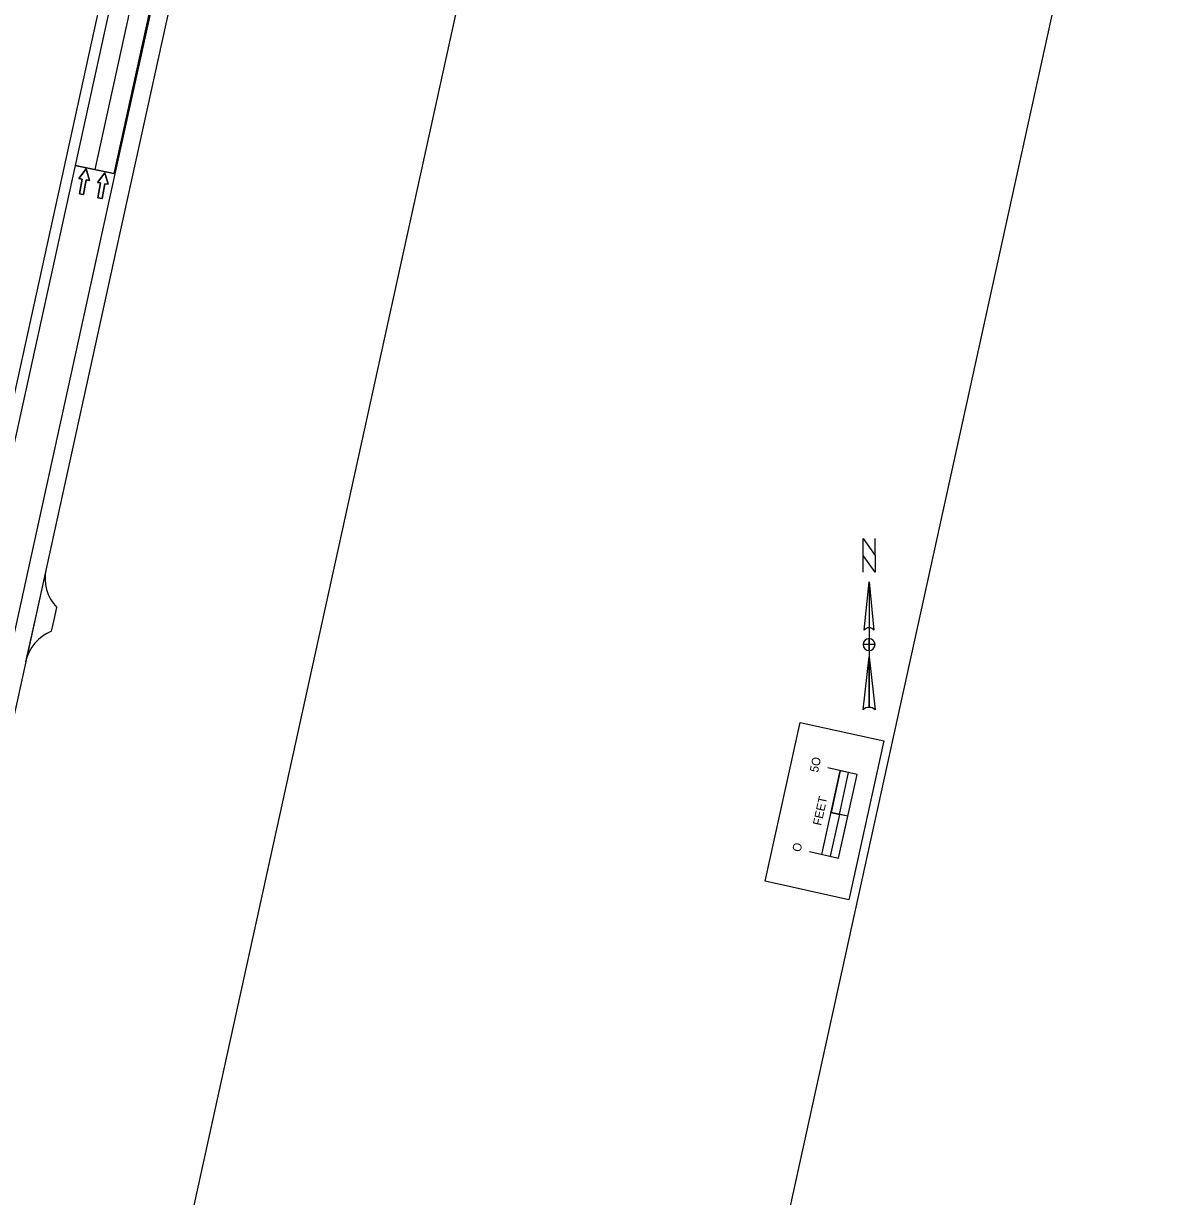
# Model space of a CAD drawing. Extents: x 14104283 to 14129344, y 8637090 to 8673339.
# Drawn here: x 14108148 to 14108813, y 8640210 to 8640895 of the extents above; entities that cross this region are included whole.
import ezdxf

# ---------------------------------------------------------------- set-up
doc = ezdxf.new("R2010")
doc.units = 0
for name, color, linetype in [('Cell', 7, 'Continuous'), ('Default', 7, 'Continuous'), ('dsnCellsNorthArrow', 7, 'Continuous'), ('dsnCellsScaleBlock', 7, 'Continuous'), ('dsnNonPlotable', 7, 'Continuous'), ('dsnPaintPlaceBrokenLineWhite', 7, 'Continuous'), ('dsnPaintPlaceEdgeLineRightWhite', 7, 'Continuous'), ('dsnShadingGranular', 7, 'Continuous'), ('dsnShadingPaved', 7, 'Continuous'), ('dsnStgShadingPrevPav', 7, 'Continuous')]:
    doc.layers.add(name, color=color, linetype=linetype)

msp = doc.modelspace()

# ---------------------------------------------------------------- linework, layer by layer
at = {"layer": 'Cell'}
for points in [[(14108183.04, 8640795.5), (14108180.58, 8640795.95), (14108182.15, 8640804.56), (14108180.3, 8640804.9), (14108184.49, 8640810.49), (14108186.45, 8640803.78), (14108184.6, 8640804.11)], [(14108193.92, 8640793.22), (14108191.46, 8640793.67), (14108193.03, 8640802.28), (14108191.19, 8640802.62), (14108195.38, 8640808.21), (14108197.33, 8640801.5), (14108195.49, 8640801.83)]]:
    msp.add_lwpolyline(points, close=True, dxfattribs=at)
for points in [[(14108184.6, 8640804.11), (14108186.45, 8640803.78), (14108184.49, 8640810.49), (14108180.3, 8640804.9), (14108182.15, 8640804.56), (14108180.58, 8640795.95), (14108183.04, 8640795.5), (14108184.6, 8640804.11)], [(14108195.49, 8640801.83), (14108197.33, 8640801.5), (14108195.38, 8640808.21), (14108191.19, 8640802.62), (14108193.03, 8640802.28), (14108191.46, 8640793.67), (14108193.92, 8640793.22), (14108195.49, 8640801.83)]]:
    msp.add_lwpolyline(points, dxfattribs=at)
at = {"layer": 'Default'}
for p, q in [((14108178.07, 8640812.51), (14108054.09, 8640248.16)), ((14108201.57, 8640807.64), (14108178.07, 8640812.51)), ((14108077.53, 8640243.01), (14108201.57, 8640807.64))]:
    msp.add_line(p, q, dxfattribs=at)
at = {"layer": 'dsnCellsNorthArrow'}
for p, q in [((14108641.86, 8640569.29), (14108644.67, 8640541.12)), ((14108641.86, 8640569.29), (14108641.86, 8640496.05)), ((14108639.04, 8640541.12), (14108639.04, 8640541.12)), ((14108639.15, 8640541.38), (14108639.67, 8640541.97)), ((14108638.34, 8640494.64), (14108641.86, 8640525.63)), ((14108641.86, 8640529.15), (14108641.86, 8640529.15))]:
    msp.add_line(p, q, dxfattribs=at)
msp.add_lwpolyline([(14108645.38, 8640574.93), (14108638.34, 8640584.79), (14108638.34, 8640594.65), (14108645.38, 8640584.79)], close=True, dxfattribs=at)
for points in [[(14108638.34, 8640574.93), (14108638.34, 8640594.65), (14108645.38, 8640584.79), (14108645.38, 8640594.65)], [(14108639.04, 8640541.12), (14108641.86, 8640569.29), (14108641.86, 8640542.53)], [(14108641.86, 8640529.15), (14108641.86, 8640532.67), (14108638.34, 8640532.67)], [(14108645.38, 8640532.67), (14108641.86, 8640532.67), (14108641.86, 8640536.19)], [(14108641.86, 8640496.05), (14108641.86, 8640525.63), (14108645.38, 8640494.64)]]:
    msp.add_lwpolyline(points, dxfattribs=at)
for centre, radius, start, end in [((14108641.86, 8640539.01), 3.52, 90.02039, 143.12574), ((14108641.86, 8640539.01), 3.52, 36.84806, 90.02184), ((14108641.86, 8640532.67), 3.52, 90, 180), ((14108641.86, 8640532.67), 3.52, 180, 270), ((14108641.86, 8640532.67), 3.52, 0, 90), ((14108641.86, 8640532.67), 3.52, 270, 360), ((14108641.86, 8640490.95), 5.1, 89.98939, 133.61895), ((14108641.86, 8640490.94), 5.11, 46.40206, 90.00064)]:
    msp.add_arc(centre, radius, start, end, dxfattribs=at)
at = {"layer": 'dsnCellsScaleBlock'}
msp.add_line((14108629.49, 8640432.47), (14108619.72, 8640434.62), dxfattribs=at)
msp.add_line((14108629.49, 8640432.47), (14108619.72, 8640434.62), dxfattribs=at)
for points in [[(14108630.04, 8640383.72), (14108581.2, 8640394.45), (14108601.59, 8640487.23), (14108650.42, 8640476.5)], [(14108581.2, 8640394.45), (14108601.59, 8640487.23), (14108650.42, 8640476.5), (14108630.04, 8640383.72)], [(14108630.04, 8640383.72), (14108581.2, 8640394.45), (14108601.59, 8640487.23), (14108650.42, 8640476.5)], [(14108624.57, 8640433.55), (14108629.93, 8640457.97), (14108625.08, 8640459.04), (14108619.72, 8640434.62)], [(14108624.12, 8640408.05), (14108629.49, 8640432.47), (14108624.57, 8640433.55), (14108619.2, 8640409.13)]]:
    msp.add_lwpolyline(points, close=True, dxfattribs=at)
for points in [[(14108607.03, 8640411.81), (14108624.12, 8640408.05), (14108634.85, 8640456.89), (14108617.76, 8640460.64)], [(14108614.35, 8640410.2), (14108625.08, 8640459.04)]]:
    msp.add_lwpolyline(points, dxfattribs=at)
at = {"layer": 'dsnNonPlotable'}
for points in [[(14107490.45, 8639880.3), (14107826.84, 8641411.28), (14108813.31, 8641194.53), (14108476.92, 8639663.55)], [(14107651.31, 8639844.94), (14107987.7, 8641375.92), (14108480.93, 8641267.54), (14108144.54, 8639736.56)]]:
    msp.add_lwpolyline(points, close=True, dxfattribs=at)
at = {"layer": 'dsnPaintPlaceBrokenLineWhite'}
msp.add_line((14108189.82, 8640810.08), (14108306.37, 8641340.66), dxfattribs=at)
at = {"layer": 'dsnPaintPlaceEdgeLineRightWhite'}
msp.add_line((14108201.57, 8640807.63), (14108723.98, 8643185.75), dxfattribs=at)
at = {"layer": 'dsnShadingGranular'}
for p, q in [((14108161.12, 8640576.89), (14108155.11, 8640549.54)), ((14108155.11, 8640549.54), (14108149.21, 8640522.69))]:
    msp.add_line(p, q, dxfattribs=at)
at = {"layer": 'dsnShadingPaved'}
for p, q in [((14108200.83, 8640807.79), (14108723.98, 8643185.75)), ((14108199.55, 8640910.32), (14108178.07, 8640812.51)), ((14108178.07, 8640812.51), (14108200.83, 8640807.79))]:
    msp.add_line(p, q, dxfattribs=at)
at = {"layer": 'dsnStgShadingPrevPav'}
for p, q in [((14108161.12, 8640576.89), (14108155.11, 8640549.54)), ((14108165.86, 8640547.18), (14108167.42, 8640554.3)), ((14108155.11, 8640549.54), (14108149.21, 8640522.69)), ((14108164.4, 8640540.56), (14108165.86, 8640547.18))]:
    msp.add_line(p, q, dxfattribs=at)
msp.add_lwpolyline([(14108081.5, 8640400.87), (14108123.34, 8640591.33), (14108126.55, 8640605.98), (14108216.67, 8641016.2), (14108268.16, 8641250.61), (14108382.95, 8641773.15), (14108422.02, 8641764.57), (14108309.38, 8641251.8), (14108270.22, 8641073.55), (14108265.93, 8641054.01), (14108255.74, 8641007.62), (14108202.1, 8640763.44), (14108120.56, 8640392.29)], close=True, dxfattribs=at)
for centre, start, end in [((14108185.53, 8640571.53), 167.61138, 223.56569), ((14108173.63, 8640517.32), 111.65473, 167.60886)]:
    msp.add_arc(centre, 25, start, end, dxfattribs=at)

# ---------------------------------------------------------------- texts
at = {"layer": 'dsnCellsScaleBlock'}
for s, p in [('5O', (14108612, 8640457.74)), ('FEET', (14108613.88, 8640426.71)), ('O', (14108601.79, 8640411.29))]:
    msp.add_text(s, height=5, rotation=77.60784, dxfattribs=at).set_placement(p)

doc.saveas('drawing.dxf')
